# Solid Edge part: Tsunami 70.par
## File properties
Title: Tsunami 70 70x45,5 cm
Author: DESYS
Template: Normal.par
Last saved by: Luca
Revision: 10
Application: Solid Edge
Tipo di contenuto documento: 0
Precisione: 0,99
Document Number: 8039
Revision: 0
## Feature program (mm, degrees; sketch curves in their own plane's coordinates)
sketch for "unnamed Protrusion 1" plane through (0, 0, -131.67) normal (0, 0, 1) x-axis (1, 0, 0)
  line (-455, 38.1919) -> (0, 38.1919)
  line (0, 38.1919) -> (0, -661.8081)
  line (0, -661.8081) -> (-455, -661.8081)
  line (-455, -661.8081) -> (-455, 38.1919)
extrude "unnamed Protrusion 1" add along +normal
sketch for "unnamed Cutout 1" plane through (-227.5, 38.1919, -54.6711) normal (0, 1, 0) x-axis (-1, 0, 0)
  arc centre (0, 4671.3691) radius 4600 from (-227.5, 76.9982) to (227.5, 76.9982) ccw
extrude "unnamed Cutout 1" cut through along -normal
sketch for "Foro_1" plane through (-227.5, -311.8081, -131.67) normal (0, 0, -1) x-axis (0, 1, 0)
  hole centre (0, 0) bore radius 25
hole "Foro_1" diameter 50 through
fillet "Rotondo_8" radius 7.5
fillet "Rotondo_9" radius 5
fillet "Rotondo_10" radius 3
thinwall "Thinwall_5"  Thickness = 20 mm
fillet "Rotondo_13" radius 10
sketch for "ExtrudedProtrusion_6" #1 plane through (-227.5, -311.8081, -116.67) normal (0, 0, -1) x-axis (0, -1, 0)
  line (-270, 207.5) -> (-270, -82.5)
  arc centre (-245, -82.5) radius 25 from (-270, -82.5) to (-245, -107.5) ccw
  line (-245, -107.5) -> (245, -107.5)
  arc centre (245, -82.5) radius 25 from (245, -107.5) to (270, -82.5) ccw
  line (270, -82.5) -> (270, 207.5)
  line (330, 207.5) -> (270, 207.5)
  line (330, -207.5) -> (330, 207.5)
  line (-330, -207.5) -> (330, -207.5)
  line (-330, 207.5) -> (-330, -207.5)
  line (-270, 207.5) -> (-330, 207.5)
sketch for "ExtrudedProtrusion_6" #2 plane through (-227.5, -311.8081, -116.67) normal (0, 0, -1) x-axis (0, -1, 0)
  line (-166.3889, 217.0154) -> (-166.3889, 162.5)
  line (-166.3889, 162.5) -> (166.3889, 162.5)
  line (166.3889, 162.5) -> (166.3889, 217.0154)
  line (-166.3889, 217.0154) -> (166.3889, 217.0154)
extrude "ExtrudedProtrusion_6" add along +normal  Profile_Plane1_Distance = 15 mm
draft "Draft_1"  Angles1 = 10 deg
fillet "Rotondo_15" radius 10
fillet "Rotondo_16" radius 5
fillet "Rotondo_17" radius 10
fillet "Rotondo_18" radius 5
sketch for "Foro_4" plane through (-227.5, -311.8081, -131.67) normal (0, 0, -1) x-axis (0, -1, 0)
  hole centre (-338, 0) bore radius 7
hole "Foro_4" finite
sketch for "unnamed Hole 1" plane through (-227.5, -311.8081, -131.67) normal (0, 0, -1) x-axis (0, -1, 0)
  hole centre (338, 207.5) bore radius 7
hole "unnamed Hole 1" finite
sketch for "unnamed Hole 2" plane through (-227.5, -311.8081, -131.67) normal (0, 0, -1) x-axis (0, -1, 0)
  hole centre (338, 0) bore radius 7
hole "unnamed Hole 2" finite
sketch for "unnamed Hole 3" plane through (-227.5, -311.8081, -131.67) normal (0, 0, -1) x-axis (0, -1, 0)
  hole centre (-338, 207.5) bore radius 7
hole "unnamed Hole 3" finite
pattern "unnamed Pattern 1" of "Foro_4", "unnamed Hole 1", "unnamed Hole 2", "unnamed Hole 3"
sketch for "unnamed Cutout 2" #1 plane through (-455, -311.8081, -54.1039) normal (-1, 0, 0) x-axis (0, -1, 0)
  line (210, -37.5661) -> (220, -37.5661)
  line (220, -17.5661) -> (210, -17.5661)
sketch for "unnamed Cutout 2" #2 plane through (-455, -311.8081, -54.1039) normal (-1, 0, 0) x-axis (0, -1, 0)
  line (-220, -37.5661) -> (-210, -37.5661)
  line (-210, -17.5661) -> (-220, -17.5661)
  dimension (linear) = 220
  dimension (linear) = 220
extrude "unnamed Cutout 2" cut through along -normal
sketch for "ExtrudedCutout_10" #1 plane through (-455, -311.8081, -54.1039) normal (-1, 0, 0) x-axis (0, -1, 0)
  line (240, -77.5661) -> (236.028, -20.764)
  arc centre (228.0475, -21.322) radius 8 from (236.028, -20.764) to (228.0475, -13.322) ccw
  line (201.9525, -13.322) -> (228.0475, -13.322)
  arc centre (201.9525, -21.322) radius 8 from (201.9525, -13.322) to (193.972, -20.764) ccw
  line (190, -77.5661) -> (193.972, -20.764)
  line (190, -77.5661) -> (240, -77.5661)
sketch for "ExtrudedCutout_10" #2 plane through (-455, -311.8081, -54.1039) normal (-1, 0, 0) x-axis (0, -1, 0)
  line (-240, -77.5661) -> (-236.028, -20.764)
  arc centre (-228.0475, -21.322) radius 8 from (-236.028, -20.764) to (-228.0475, -13.322) cw
  line (-201.9525, -13.322) -> (-228.0475, -13.322)
  arc centre (-201.9525, -21.322) radius 8 from (-201.9525, -13.322) to (-193.972, -20.764) cw
  line (-190, -77.5661) -> (-193.972, -20.764)
  line (-240, -77.5661) -> (-190, -77.5661)
extrude "ExtrudedCutout_10" cut finite 5 along -normal
sketch for "unnamed Hole 4" plane through (-455, -311.8081, -54.1039) normal (-1, 0, 0) x-axis (0, -1, 0)
  hole centre (320, -47.5661) bore radius 5
  dimension (linear) = 320
hole "unnamed Hole 4" finite
pattern "unnamed Pattern 2" of "unnamed Hole 4"
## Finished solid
Body 1: solid body, 123 faces, 282 edges, 160 vertices.
  Faces by surface: cylinder 45, plane 37, blend 24, torus 7, sphere 6, cone 2, offset 1, spline 1
  Edges by curve: line 112, circle 89, intersection 71, ellipse 10
Body 2: sheet body, 1 face, 4 edges, 4 vertices.
  Faces by surface: spline 1
  Edges by curve: circle 2, spline 2
Bounding box of the edges (mm; curved faces can reach further): 455.000 x 700.000 x 153.998, from (-455, -661.8081, -131.671) to (0.0004, 38.1919, 22.3271).
Cylindrical faces by radius (mm): R5 x21, R7 x4, R8 x4, R10 x12, R25 x1, R45 x1, R4600 x2
Conical faces (half-angle, radius in mm at the cone's reference point): 10 deg R25 x2
Toroidal faces (ring radius, tube radius in mm): R15 r5 x2, R33.391 r10 x2, R35 r10 x1, R4607.5 r7.5 x2
Spherical faces by radius (mm): R5 x4, R10 x2
Planar faces by outward normal: +x 2, +y 2, +z 2, -x 5, -y 2, -z 13, oblique 11
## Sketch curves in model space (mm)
arc centre (-455, -311.8081, 2264.3477) radius 2269.1752 from (-455, 38.1919, 22.3271) through (-455, -311.8081, -4.8275) to (-455, -661.8081, 22.3271)
arc centre (-227.5, -311.8081, 477.533) radius 574.2059 from (-227.5, -661.8081, 22.3271) through (-227.5, -311.8081, -96.6729) to (-227.5, 38.1919, 22.3271)
arc centre (0, -311.8081, 1222.3271) radius 1250 from (0, -661.8081, 22.3271) through (0, -311.8081, -27.6729) to (0, 38.1919, 22.3271)
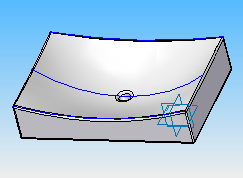
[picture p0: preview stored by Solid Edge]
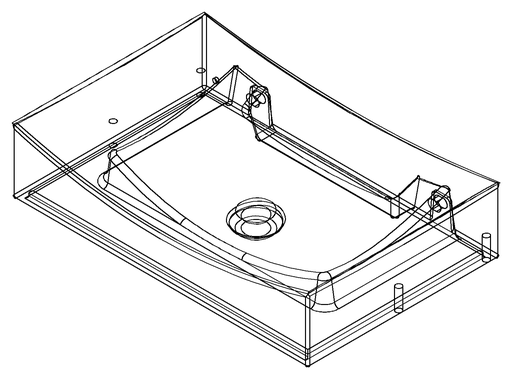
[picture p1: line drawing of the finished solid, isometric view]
